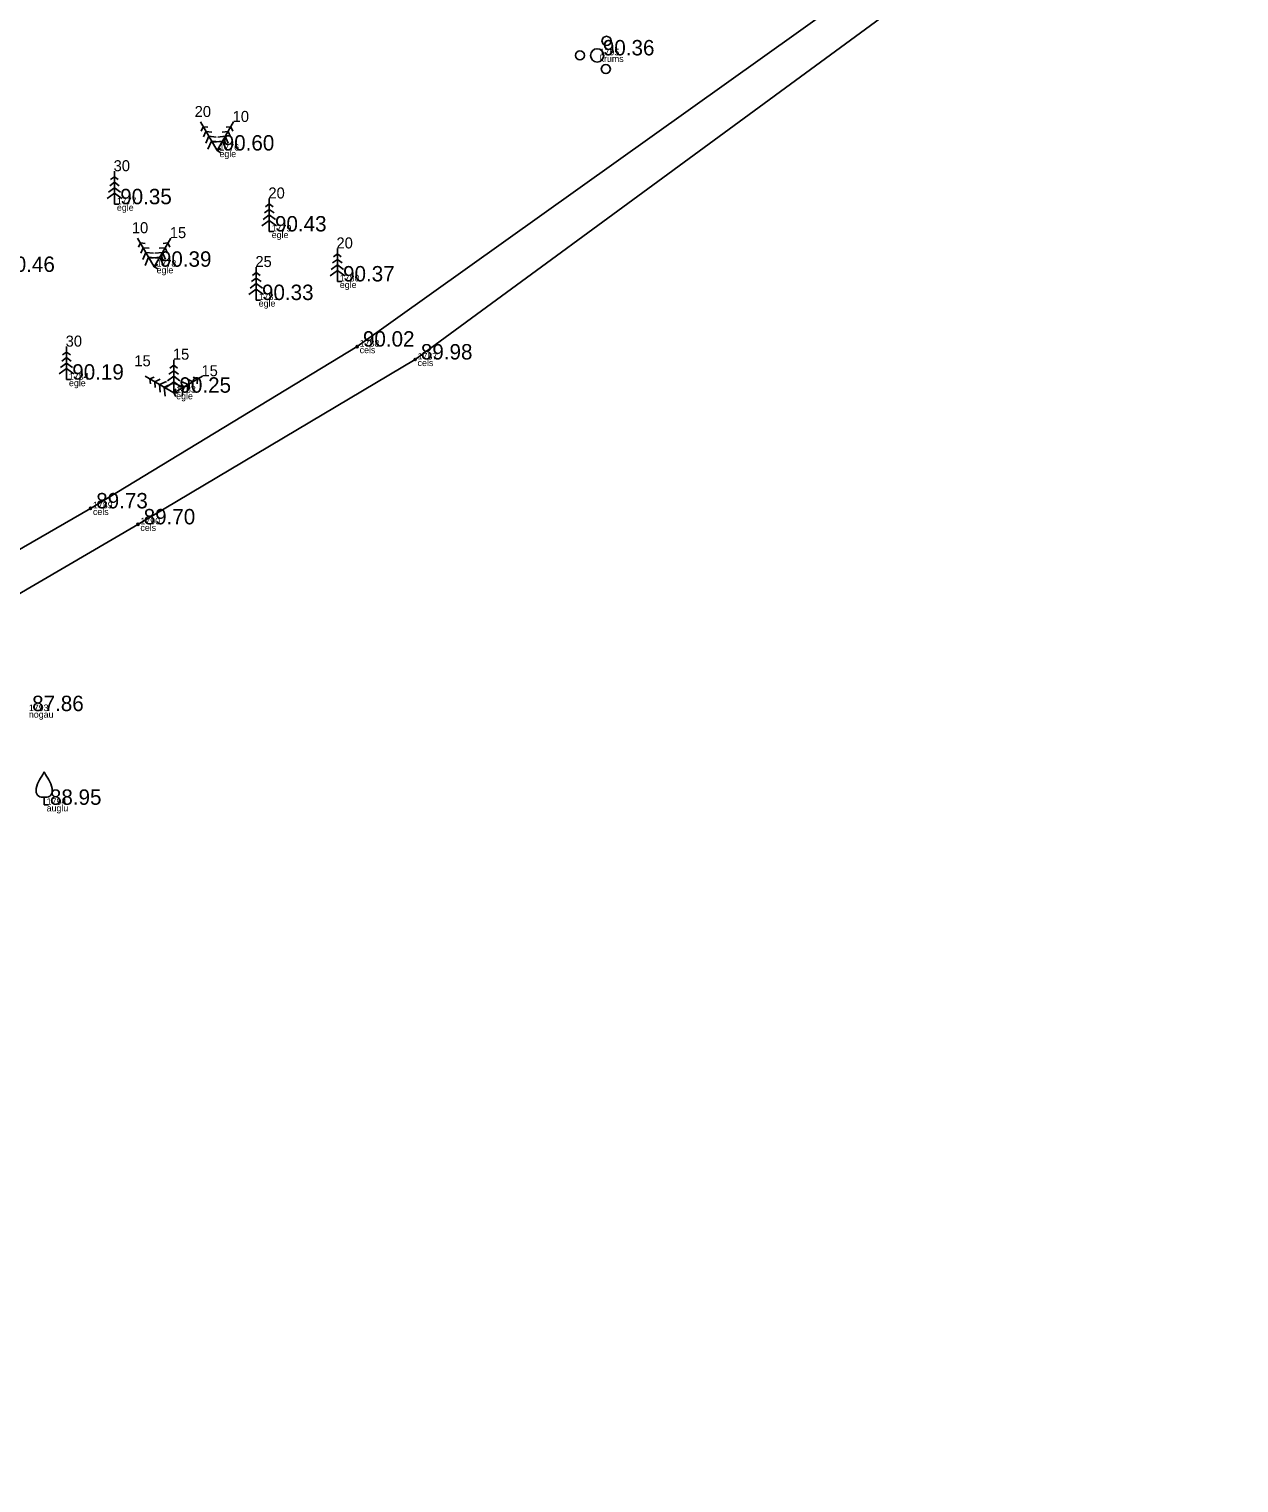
# Model space of a CAD drawing. Extents: x 614911 to 615803, y 262110 to 264311.
# Drawn here: x 615689.6 to 615744.6, y 263442.2 to 263508.2 of the extents above; entities that cross this region are included whole.
import ezdxf

# ---------------------------------------------------------------- set-up
doc = ezdxf.new("R2010")
doc.units = 0
for name, color, linetype in [('Level 1', 7, 'Continuous'), ('Level 37', 7, 'Continuous'), ('Level 53', 7, 'Continuous'), ('Level 54', 7, 'Continuous'), ('Level 57', 7, 'Continuous'), ('Level 58', 7, 'Continuous')]:
    doc.layers.add(name, color=color, linetype=linetype)

msp = doc.modelspace()

# ---------------------------------------------------------------- linework, layer by layer
at = {"layer": 'Level 1'}
for p, q in [((615697.434, 263503.995), (615698.184, 263502.696)), ((615697.559, 263503.779), (615697.471, 263503.58)), ((615697.559, 263503.779), (615697.774, 263503.755)), ((615698.934, 263503.995), (615698.184, 263502.696)), ((615698.809, 263503.779), (615698.593, 263503.756)), ((615698.809, 263503.779), (615698.896, 263503.581)), ((615697.684, 263503.562), (615697.576, 263503.317)), ((615697.809, 263503.346), (615697.67, 263503.03)), ((615697.684, 263503.562), (615697.95, 263503.533)), ((615697.934, 263503.129), (615697.768, 263502.752)), ((615697.809, 263503.346), (615698.152, 263503.308)), ((615697.934, 263503.129), (615698.345, 263503.085)), ((615698.434, 263503.129), (615698.024, 263503.084)), ((615698.559, 263503.346), (615698.216, 263503.308)), ((615698.684, 263503.562), (615698.418, 263503.533)), ((615698.434, 263503.129), (615698.601, 263502.751)), ((615698.559, 263503.346), (615698.698, 263503.03)), ((615698.684, 263503.562), (615698.792, 263503.317)), ((615698.184, 263502.696), (615698.357, 263502.796)), ((615698.184, 263502.696), (615698.357, 263502.596)), ((615693.527, 263501.757), (615693.527, 263500.257)), ((615693.527, 263501.257), (615693.311, 263501.099)), ((615693.527, 263501.507), (615693.351, 263501.379)), ((615693.527, 263501.507), (615693.701, 263501.379)), ((615693.527, 263501.257), (615693.743, 263501.099)), ((615693.527, 263500.757), (615693.195, 263500.513)), ((615693.527, 263501.007), (615693.249, 263500.803)), ((615693.527, 263501.007), (615693.805, 263500.803)), ((615693.527, 263500.757), (615693.861, 263500.513)), ((615700.558, 263500.519), (615700.558, 263499.019)), ((615693.527, 263500.257), (615693.727, 263500.257)), ((615700.558, 263499.769), (615700.28, 263499.565)), ((615700.558, 263500.019), (615700.342, 263499.861)), ((615700.558, 263500.269), (615700.382, 263500.141)), ((615700.558, 263500.269), (615700.732, 263500.141)), ((615700.558, 263500.019), (615700.774, 263499.861)), ((615700.558, 263499.769), (615700.836, 263499.565)), ((615700.558, 263499.519), (615700.226, 263499.275)), ((615700.558, 263499.519), (615700.892, 263499.275)), ((615694.58, 263498.716), (615695.33, 263497.417)), ((615694.705, 263498.5), (615694.617, 263498.301)), ((615694.705, 263498.5), (615694.92, 263498.476)), ((615696.08, 263498.716), (615695.33, 263497.417)), ((615695.955, 263498.5), (615695.739, 263498.477)), ((615695.955, 263498.5), (615696.042, 263498.302)), ((615700.558, 263499.019), (615700.758, 263499.019)), ((615694.83, 263498.283), (615694.722, 263498.038)), ((615694.955, 263498.067), (615694.816, 263497.751)), ((615694.83, 263498.283), (615695.096, 263498.254)), ((615695.08, 263497.85), (615694.914, 263497.473)), ((615694.955, 263498.067), (615695.298, 263498.029)), ((615695.08, 263497.85), (615695.491, 263497.806)), ((615695.58, 263497.85), (615695.17, 263497.805)), ((615695.705, 263498.067), (615695.362, 263498.029)), ((615695.83, 263498.283), (615695.564, 263498.254)), ((615695.58, 263497.85), (615695.747, 263497.472)), ((615695.705, 263498.067), (615695.844, 263497.751)), ((615695.83, 263498.283), (615695.938, 263498.038)), ((615703.65, 263497.749), (615703.434, 263497.591)), ((615703.65, 263497.999), (615703.474, 263497.871)), ((615703.65, 263498.249), (615703.65, 263496.749)), ((615703.65, 263497.999), (615703.824, 263497.871)), ((615703.65, 263497.749), (615703.866, 263497.591)), ((615695.33, 263497.417), (615695.503, 263497.517)), ((615695.33, 263497.417), (615695.503, 263497.317)), ((615699.967, 263497.154), (615699.791, 263497.026)), ((615699.967, 263497.404), (615699.967, 263495.904)), ((615699.967, 263497.154), (615700.141, 263497.026)), ((615703.65, 263497.249), (615703.318, 263497.005)), ((615703.65, 263497.499), (615703.372, 263497.295)), ((615703.65, 263497.499), (615703.928, 263497.295)), ((615703.65, 263497.249), (615703.984, 263497.005)), ((615699.967, 263496.654), (615699.689, 263496.45)), ((615699.967, 263496.904), (615699.751, 263496.746)), ((615699.967, 263496.904), (615700.183, 263496.746)), ((615699.967, 263496.654), (615700.245, 263496.45)), ((615703.65, 263496.749), (615703.85, 263496.749)), ((615699.967, 263496.404), (615699.635, 263496.16)), ((615699.967, 263496.404), (615700.301, 263496.16)), ((615699.967, 263495.904), (615700.167, 263495.904)), ((615691.349, 263493.788), (615691.349, 263492.288)), ((615691.349, 263493.288), (615691.133, 263493.13)), ((615691.349, 263493.538), (615691.173, 263493.41)), ((615691.349, 263493.538), (615691.523, 263493.41)), ((615691.349, 263493.288), (615691.565, 263493.13)), ((615696.219, 263493.194), (615696.219, 263491.694)), ((615691.349, 263492.788), (615691.017, 263492.544)), ((615691.349, 263493.038), (615691.071, 263492.834)), ((615691.349, 263493.038), (615691.627, 263492.834)), ((615691.349, 263492.788), (615691.683, 263492.544)), ((615696.219, 263492.694), (615696.003, 263492.536)), ((615696.219, 263492.944), (615696.043, 263492.816)), ((615696.219, 263492.944), (615696.393, 263492.816)), ((615696.219, 263492.694), (615696.435, 263492.536)), ((615691.349, 263492.288), (615691.549, 263492.288)), ((615694.92, 263492.444), (615696.219, 263491.694)), ((615695.136, 263492.319), (615695.334, 263492.406)), ((615695.136, 263492.319), (615695.159, 263492.103)), ((615695.353, 263492.194), (615695.598, 263492.302)), ((615695.353, 263492.194), (615695.382, 263491.928)), ((615695.569, 263492.069), (615695.885, 263492.208)), ((615695.569, 263492.069), (615695.607, 263491.726)), ((615695.786, 263491.944), (615696.164, 263492.111)), ((615695.786, 263491.944), (615695.831, 263491.534)), ((615696.219, 263492.194), (615695.887, 263491.95)), ((615696.219, 263492.444), (615695.941, 263492.24)), ((615696.219, 263492.444), (615696.497, 263492.24)), ((615697.518, 263492.444), (615696.219, 263491.694)), ((615696.219, 263492.194), (615696.553, 263491.95)), ((615696.219, 263491.694), (615696.319, 263491.867)), ((615696.652, 263491.944), (615696.275, 263492.11)), ((615696.869, 263492.069), (615696.553, 263492.208)), ((615696.652, 263491.944), (615696.608, 263491.533)), ((615696.869, 263492.069), (615696.831, 263491.726)), ((615697.085, 263492.194), (615696.84, 263492.302)), ((615697.085, 263492.194), (615697.056, 263491.928)), ((615697.302, 263492.319), (615697.103, 263492.407)), ((615697.302, 263492.319), (615697.278, 263492.104)), ((615696.219, 263491.694), (615696.419, 263491.694)), ((615696.219, 263491.694), (615696.319, 263491.521)), ((615690.334, 263473.323), (615690.334, 263472.971)), ((615690.334, 263472.971), (615690.534, 263472.971))]:
    msp.add_line(p, q, dxfattribs=at)
for centre, radius in [((615715.878, 263507.679), 0.207), ((615714.667, 263507.019), 0.204), ((615715.451, 263507.019), 0.301), ((615715.846, 263506.399), 0.205)]:
    msp.add_circle(centre, radius, dxfattribs=at)
for centre, radius, start, end in [((615690.858, 263473.596), 0.89, 151.75703, 179.91384), ((615702.959, 263466.575), 14.88, 148.48442, 149.99014), ((615689.917, 263474.609), 0.439, 324.38368, 341.71196), ((615690.751, 263474.609), 0.439, 198.28804, 215.61632), ((615677.709, 263466.575), 14.88, 30.00986, 31.51558), ((615689.81, 263473.596), 0.89, 0.08616, 28.24297), ((615690.258, 263473.602), 0.29, 181.07816, 285.2823), ((615690.41, 263473.602), 0.29, 254.7177, 358.92184)]:
    msp.add_arc(centre, radius, start, end, dxfattribs=at)
at = {"layer": 'Level 37'}
for points in [[(615640.593, 263444.077), (615645.77, 263448.925), (615656.412, 263459.375), (615662.104, 263464.753), (615672.019, 263472.421), (615683.77, 263481.412), (615685.947, 263482.698), (615692.438, 263486.438), (615704.553, 263493.789), (615734.729, 263515.331), (615744.043, 263521.815)], [(615642.494, 263442.163), (615647.437, 263447.751), (615657.328, 263457.944), (615663.266, 263463.435), (615673.138, 263471.007), (615685.255, 263480.126), (615686.777, 263481.148), (615694.593, 263485.712), (615707.185, 263493.203), (615735.25, 263513.819), (615744.602, 263520.653)]]:
    msp.add_lwpolyline(points, dxfattribs=at)
at = {"layer": 'Level 57'}
for centre in [(615704.553, 263493.789), (615707.185, 263493.203), (615692.438, 263486.438), (615694.593, 263485.712)]:
    msp.add_circle(centre, 0.05, dxfattribs=at)
at = {"layer": 'Level 58'}
for centre in [(615704.553, 263493.789), (615707.185, 263493.203), (615692.438, 263486.438), (615694.593, 263485.712)]:
    msp.add_circle(centre, 0.05, dxfattribs=at)

# ---------------------------------------------------------------- texts
at = {"layer": 'Level 1'}
for s, p in [(' 20', (615696.984, 263504.22)), (' 10', (615698.709, 263503.995)), (' 30', (615693.302, 263501.757)), (' 20', (615700.333, 263500.519)), (' 10', (615694.13, 263498.941)), (' 15', (615695.855, 263498.716)), (' 20', (615703.425, 263498.249)), (' 25', (615699.742, 263497.404)), (' 30', (615691.124, 263493.788)), (' 15', (615694.245, 263492.894)), (' 15', (615695.994, 263493.194)), (' 15', (615697.293, 263492.444))]:
    msp.add_text(s, height=0.5, dxfattribs=at).set_placement(p)
at = {"layer": 'Level 53'}
for s, p in [(' krums', (615715.451, 263506.719)), (' egle', (615698.184, 263502.396)), (' egle', (615693.527, 263499.957)), (' egle', (615700.558, 263498.719)), (' egle', (615695.33, 263497.117)), (' egle', (615703.65, 263496.449)), (' egle', (615699.967, 263495.604)), (' cels', (615704.553, 263493.489)), (' cels', (615707.185, 263492.903)), (' egle', (615691.349, 263491.988)), (' egle', (615696.219, 263491.394)), (' cels', (615692.438, 263486.138)), (' cels', (615694.593, 263485.412)), (' nogau', (615689.528, 263476.928)), (' auglu', (615690.334, 263472.671))]:
    msp.add_text(s, height=0.3, dxfattribs=at).set_placement(p)
at = {"layer": 'Level 54'}
for s, p in [(' 1795', (615715.451, 263507.019)), (' 1776', (615698.184, 263502.696)), (' 1777', (615693.527, 263500.257)), (' 1779', (615700.558, 263499.019)), (' 1778', (615695.33, 263497.417)), (' 1780', (615703.65, 263496.749)), (' 1781', (615699.967, 263495.904)), (' 1788', (615704.553, 263493.789)), (' 1787', (615707.185, 263493.203)), (' 1784', (615691.349, 263492.288)), (' 1783', (615696.219, 263491.694)), (' 1789', (615692.438, 263486.438)), (' 1790', (615694.593, 263485.712)), (' 1793', (615689.528, 263477.228)), (' 1794', (615690.334, 263472.971))]:
    msp.add_text(s, height=0.3, dxfattribs=at).set_placement(p)
at = {"layer": 'Level 58'}
for s, p in [(' 90.36', (615715.451, 263507.019)), (' 90.60', (615698.184, 263502.696)), (' 90.35', (615693.527, 263500.257)), (' 90.43', (615700.558, 263499.019)), (' 90.46', (615688.216, 263497.182)), (' 90.39', (615695.33, 263497.417)), (' 90.37', (615703.65, 263496.749)), (' 90.33', (615699.967, 263495.904)), (' 90.02', (615704.553, 263493.789)), (' 89.98', (615707.185, 263493.203)), (' 90.19', (615691.349, 263492.288)), (' 90.25', (615696.219, 263491.694)), (' 89.73', (615692.438, 263486.438)), (' 89.70', (615694.593, 263485.712)), (' 87.86', (615689.528, 263477.228)), (' 88.95', (615690.334, 263472.971))]:
    msp.add_text(s, height=0.7, dxfattribs=at).set_placement(p)

doc.saveas('drawing.dxf')
